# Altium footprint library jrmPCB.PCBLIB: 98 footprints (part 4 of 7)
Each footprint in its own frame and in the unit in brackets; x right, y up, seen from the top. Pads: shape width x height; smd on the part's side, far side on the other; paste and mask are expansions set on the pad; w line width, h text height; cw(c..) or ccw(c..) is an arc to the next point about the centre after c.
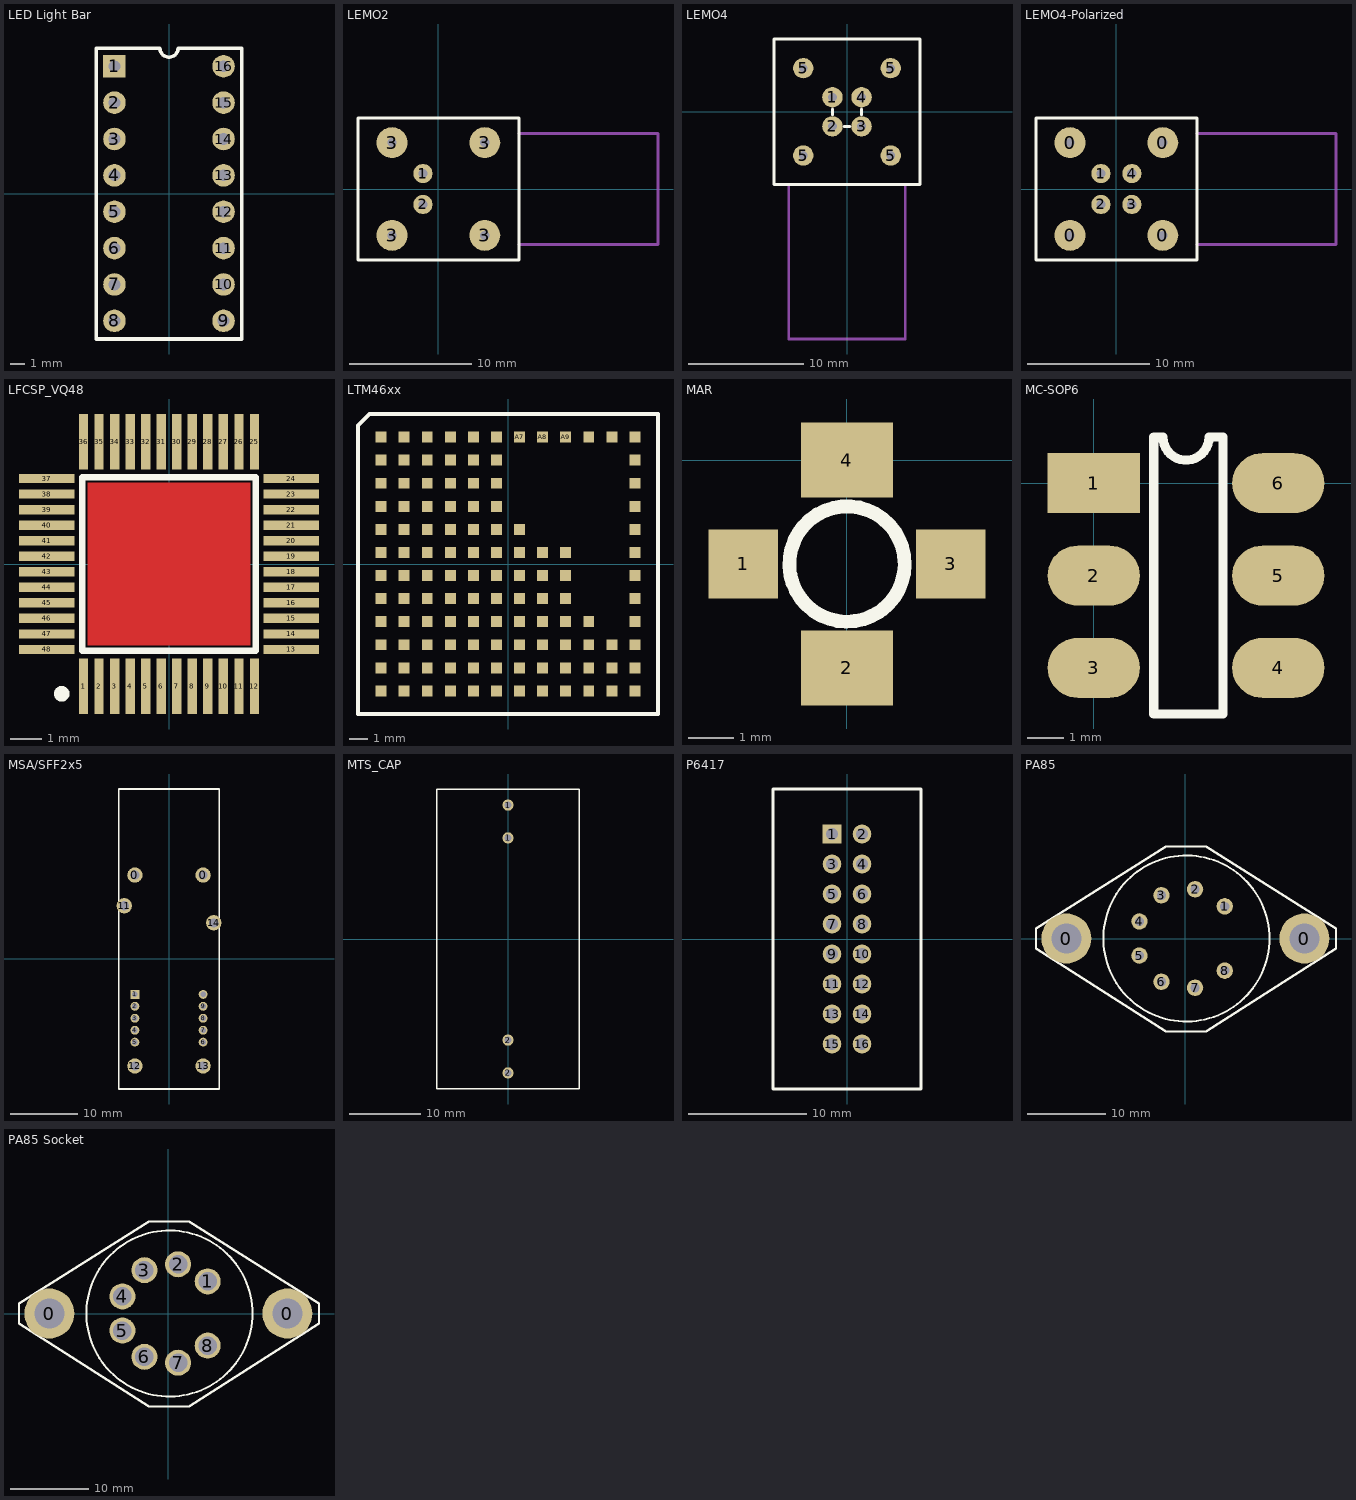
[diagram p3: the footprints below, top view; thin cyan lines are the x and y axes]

## LED Light Bar [mil]
pads (16):
  rect 62x62 hole 32: 1(-150,350)
  round 62 hole 32: 2(-150,250) 3(-150,150) 4(-150,50) 5(-150,-50) 6(-150,-150) 7(-150,-250) 8(-150,-350) 9(150,-350) 10(150,-250) 11(150,-150) 12(150,-50) 13(150,50) 14(150,150) 15(150,250) 16(150,350)
Top Overlay:
  lines w10: -200,-400 200,-400 200,400 25,400 cw(c0,400) -25,400 -200,400 -200,-400

## LEMO2 [mil] "2 pin LEMO connector"
pads (6):
  round 62 hole 30: 1(-50,50) 2(-50,-50)
  round 100 hole 30: 3(-150,-150) 3(-150,150) 3(150,-150) 3(150,150)
Top Overlay:
  lines w10: -260,-230 -260,230 260,230 260,-230 -260,-230
Mechanical 1:
  lines w10: 260,-180 710,-180 710,180 260,180

## LEMO4 [mil]
pads (8):
  round 70 hole 30: 1(-50,50) 2(-50,-50) 3(50,-50) 4(50,50) 5(-150,-150) 5(-150,150) 5(150,-150) 5(150,150)
Top Overlay:
  lines w10: -50,-10 -50,10 ; -10,-50 10,-50 ; 50,-10 50,10 ; -250,-250 -250,250 250,250 250,-250 -250,-250
Mechanical 1:
  lines w10: -200,-250 -200,-780 200,-780 200,-250

## LEMO4-Polarized [mil]
pads (8):
  round 100 hole 30: 0(-150,-150) 0(-150,150) 0(150,-150) 0(150,150)
  round 62 hole 30: 1(-50,50) 2(-50,-50) 3(50,-50) 4(50,50)
Top Overlay:
  lines w10: -260,-230 -260,230 260,230 260,-230 -260,-230
Mechanical 1:
  lines w10: 260,-180 710,-180 710,180 260,180

## LFCSP_VQ48 [mil]
pads (48):
  rect 11.81x70 smd: 1(-108.27,-155) 2(-88.58,-155) 3(-68.9,-155) 4(-49.21,-155) 5(-29.53,-155) 6(-9.84,-155) 7(9.84,-155) 8(29.53,-155) 9(49.21,-155) 10(68.9,-155) 11(88.58,-155) 12(108.27,-155) 25(108.27,155) 26(88.58,155) 27(68.9,155) 28(49.21,155) 29(29.53,155) 30(9.84,155) 31(-9.84,155) 32(-29.53,155) 33(-49.21,155) 34(-68.9,155) 35(-88.58,155) 36(-108.27,155)
  rect 70x11.81 smd: 13(155,-108.27) 14(155,-88.58) 15(155,-68.9) 16(155,-49.21) 17(155,-29.53) 18(155,-9.84) 19(155,9.84) 20(155,29.53) 21(155,49.21) 22(155,68.9) 23(155,88.58) 24(155,108.27) 37(-155,108.27) 38(-155,88.58) 39(-155,68.9) 40(-155,49.21) 41(-155,29.53) 42(-155,9.84) 43(-155,-9.84) 44(-155,-29.53) 45(-155,-49.21) 46(-155,-68.9) 47(-155,-88.58) 48(-155,-108.27)
Top Layer:
  rectangle: -103.35,-103.35 103.35,103.35
Top Overlay:
  circle w9.84: c-135.83,-164.37 r4.92
  lines w7.87: -110,-110 110,-110 110,110 -110,110 -110,-110

## LTM46xx [mm]
pads (118):
  rect 0.6x0.6 smd: A7(0.635,6.985) A8(1.905,6.985) A9(3.175,6.985) A10(4.445,6.985) A11(5.715,6.985) A12(6.985,6.985) B12(6.985,5.715) "Bank 1"(-6.985,4.445) "Bank 1"(-6.985,5.715) "Bank 1"(-6.985,6.985) "Bank 1"(-5.715,4.445) "Bank 1"(-5.715,5.715) "Bank 1"(-5.715,6.985) "Bank 1"(-4.445,4.445) "Bank 1"(-4.445,5.715) "Bank 1"(-4.445,6.985) "Bank 1"(-3.175,4.445) "Bank 1"(-3.175,5.715) "Bank 1"(-3.175,6.985) "Bank 1"(-1.905,4.445) "Bank 1"(-1.905,5.715) "Bank 1"(-1.905,6.985) "Bank 1"(-0.635,4.445) "Bank 1"(-0.635,5.715) "Bank 1"(-0.635,6.985) "Bank 2"(-6.985,-1.905) "Bank 2"(-6.985,-0.635) "Bank 2"(-6.985,0.635) "Bank 2"(-6.985,1.905) "Bank 2"(-6.985,3.175) "Bank 2"(-5.715,-1.905) "Bank 2"(-5.715,-0.635) "Bank 2"(-5.715,0.635) "Bank 2"(-5.715,1.905) "Bank 2"(-5.715,3.175) "Bank 2"(-4.445,-1.905) "Bank 2"(-4.445,-0.635) "Bank 2"(-4.445,0.635) "Bank 2"(-4.445,1.905) "Bank 2"(-4.445,3.175) "Bank 2"(-3.175,-1.905) "Bank 2"(-3.175,-0.635) "Bank 2"(-3.175,0.635) "Bank 2"(-3.175,1.905) "Bank 2"(-3.175,3.175) "Bank 2"(-1.905,-1.905) "Bank 2"(-1.905,-0.635) "Bank 2"(-1.905,0.635) "Bank 2"(-1.905,1.905) "Bank 2"(-1.905,3.175) "Bank 2"(-0.635,-1.905) "Bank 2"(-0.635,-0.635) "Bank 2"(-0.635,0.635) "Bank 2"(-0.635,1.905) "Bank 2"(-0.635,3.175) "Bank 2"(0.635,-1.905) "Bank 2"(0.635,-0.635) "Bank 2"(0.635,0.635) "Bank 2"(0.635,1.905) "Bank 2"(1.905,-1.905) "Bank 2"(1.905,-0.635) "Bank 2"(1.905,0.635) "Bank 2"(3.175,-1.905) "Bank 2"(3.175,-0.635) "Bank 2"(3.175,0.635) "Bank 3"(-6.985,-6.985) "Bank 3"(-6.985,-5.715) "Bank 3"(-6.985,-4.445) "Bank 3"(-6.985,-3.175) "Bank 3"(-5.715,-6.985) "Bank 3"(-5.715,-5.715) "Bank 3"(-5.715,-4.445) "Bank 3"(-5.715,-3.175) "Bank 3"(-4.445,-6.985) "Bank 3"(-4.445,-5.715) "Bank 3"(-4.445,-4.445) "Bank 3"(-4.445,-3.175) "Bank 3"(-3.175,-6.985) "Bank 3"(-3.175,-5.715) "Bank 3"(-3.175,-4.445) "Bank 3"(-3.175,-3.175) "Bank 3"(-1.905,-6.985) "Bank 3"(-1.905,-5.715) "Bank 3"(-1.905,-4.445) "Bank 3"(-1.905,-3.175) "Bank 3"(-0.635,-6.985) "Bank 3"(-0.635,-5.715) "Bank 3"(-0.635,-4.445) "Bank 3"(-0.635,-3.175) "Bank 3"(0.635,-6.985) "Bank 3"(0.635,-5.715) "Bank 3"(0.635,-4.445) "Bank 3"(0.635,-3.175) "Bank 3"(1.905,-6.985) "Bank 3"(1.905,-5.715) "Bank 3"(1.905,-4.445) "Bank 3"(1.905,-3.175) "Bank 3"(3.175,-6.985) "Bank 3"(3.175,-5.715) "Bank 3"(3.175,-4.445) "Bank 3"(3.175,-3.175) "Bank 3"(4.445,-6.985) "Bank 3"(4.445,-5.715) "Bank 3"(4.445,-4.445) "Bank 3"(4.445,-3.175) "Bank 3"(5.715,-6.985) "Bank 3"(5.715,-5.715) "Bank 3"(5.715,-4.445) C12(6.985,4.445) D12(6.985,3.175) E12(6.985,1.905) F12(6.985,0.635) G12(6.985,-0.635) H12(6.985,-1.905) J12(6.985,-3.175) K12(6.985,-4.445) L12(6.985,-5.715) M12(6.985,-6.985)
Top Overlay:
  lines w0.2: -8.255,-8.255 8.255,-8.255 8.255,8.255 -7.62,8.255 -8.255,7.62 -8.255,-8.255

## MAR [mil]
pads (4):
  rect 60x60 smd: 1(-90,-90) 3(90,-90)
  rect 80x65 smd: 2(0,-180) 4(0,0)
Top Overlay:
  lines w12: 27.96,-131.45 cw(c0,-90) 30.09,-129.93

## MC-SOP6 [mil] "Mini Circuits SOP6 Footprint"
height 0.23
pads (6):
  rect 100x65 smd: 1(0,0)
  oval 100x65 smd: 2(0,-100) 3(0,-200) 4(200,-200) 5(200,-100) 6(200,0)
Top Overlay:
  lines w10: 65,-250 140,-250 140,50 125,50 cw(c100,50) 75,50 65,50 65,-250

## MSA/SFF2x5 [mil]
height 400
pads (16):
  round 90 hole 53: 0(-200,490) 0(200,490) 11(-262.5,310) 12(-200,-630) 13(200,-630) 14(262.5,210)
  rect 52x52 hole 32: 1(-200,-210)
  round 52 hole 32: 2(-200,-280) 3(-200,-350) 4(-200,-420) 5(-200,-490) 6(200,-490) 7(200,-420) 8(200,-350) 9(200,-280) 10(200,-210)
Top Overlay:
  lines w10: -294,-765 294,-765 294,995 -294,995 -294,-765

## MTS_CAP [mil] "Big cap for the MTS"
pads (4):
  round 62 hole 40: 1(0,557.09) 1(0,738.19) 2(0,-738.19) 2(0,-557.09)
Top Overlay:
  lines w7.87: -393.7,-826.77 393.7,-826.77 393.7,826.77 -393.7,826.77 -393.7,612.2 -393.7,-826.77

## P6417 [mil]
pads (16):
  rect 62x63 hole 40: 1(-50,350)
  oval 62x63 hole 40: 2(50,350) 3(-50,250) 4(50,250) 5(-50,150) 6(50,150) 7(-50,50) 8(50,50) 9(-50,-50) 10(50,-50) 11(-50,-150) 12(50,-150) 13(-50,-250) 14(50,-250) 15(-50,-350) 16(50,-350)
Top Overlay:
  lines w10: -25,500 246,500 246,-500 -246,-500 -246,500 25,500

## PA85 [mil]
pads (10):
  round 250 hole 150: 0(-595,0) 0(595,0)
  round 82 hole 46: 1(196.51,160.7) 2(48.41,246.2) 3(-120,216.51) 4(-229.92,85.5) 5(-229.92,-85.5) 6(-120,-216.51) 7(48.41,-246.2) 8(196.51,-160.7)
Top Overlay:
  circle w10: c5,0 r415
  circle w10: c595,0 r95
  circle w10: c-595,0 r95
  lines w12: -747,-50 -97,-465 103,-465 753,-50 753,50 103,460 -97,460 -747,50 -747,-50

## PA85 Socket [mil]
pads (10):
  round 250 hole 150: 0(-595,0) 0(595,0)
  round 130 hole 93: 1(196.51,160.7) 2(48.41,246.2) 3(-120,216.51) 4(-229.92,85.5) 5(-229.92,-85.5) 6(-120,-216.51) 7(48.41,-246.2) 8(196.51,-160.7)
Top Overlay:
  circle w10: c-595,0 r95
  circle w10: c595,0 r95
  circle w10: c5,0 r415
  lines w12: -747,-50 -747,50 -97,460 103,460 753,50 753,-50 103,-465 -97,-465 -747,-50

## PCBComponent_1 [mil]

## PCBComponent_1 - duplicate [mil]

## PCBComponent_1 - duplicate1 [mil]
